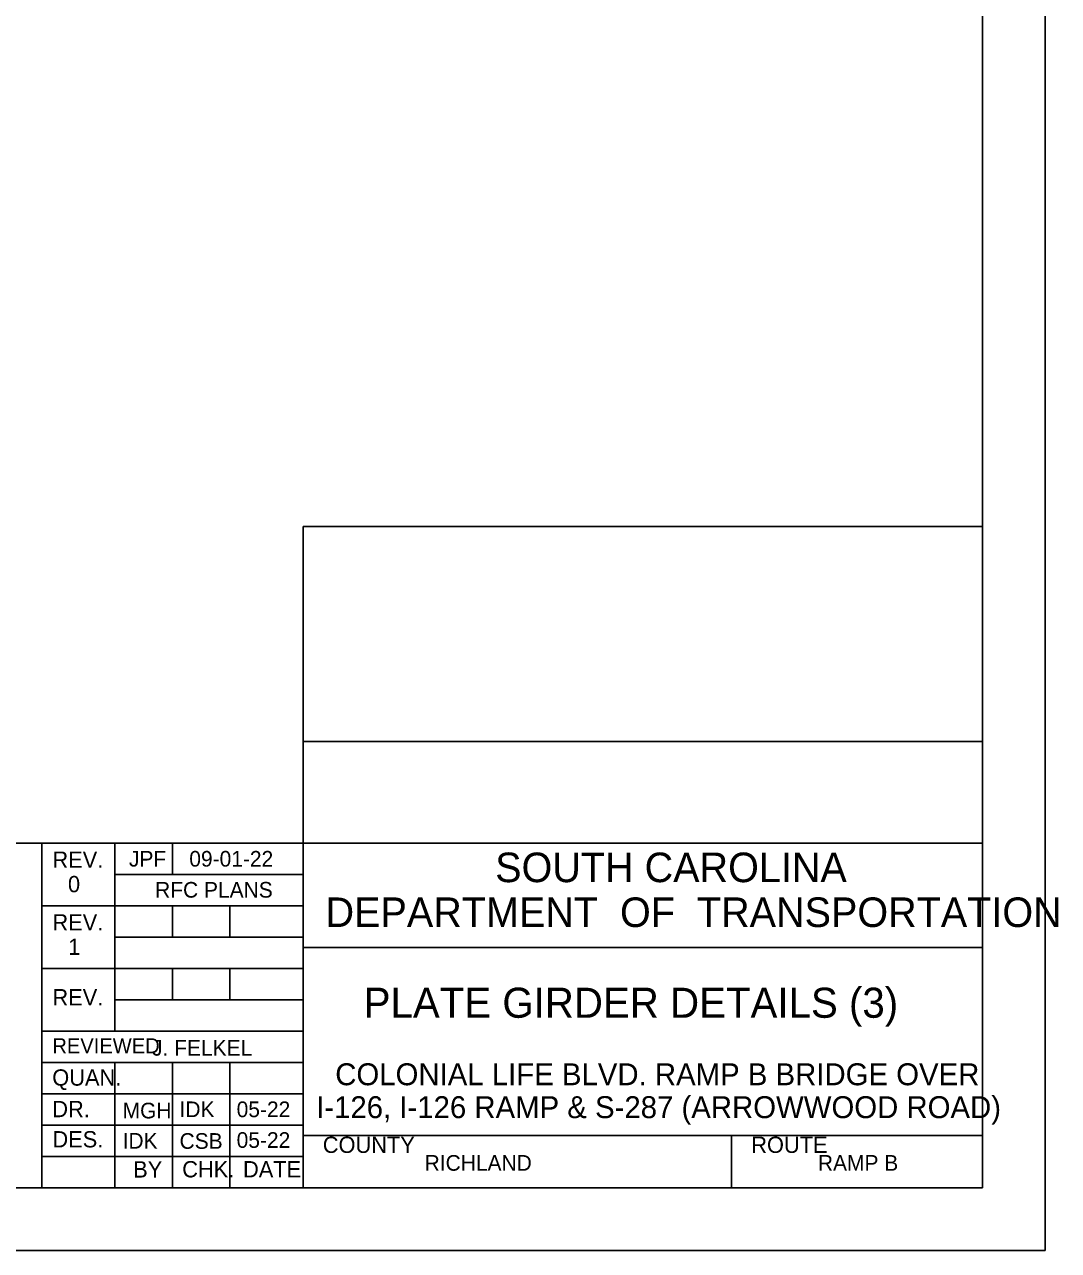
# Model space of a CAD drawing. Extents: x -305 to -161, y -187 to -99.
# Drawn here: x -193.73 to -160.75, y -187.49 to -148.37 of the extents above; entities that cross this region are included whole.
import ezdxf

# ---------------------------------------------------------------- set-up
doc = ezdxf.new("R2010")
doc.units = 0
for name, color, linetype in [('BR_BORDER LINES', 7, 'Continuous'), ('BR_TEXT', 7, 'Continuous'), ('Level 31', 7, 'Continuous')]:
    doc.layers.add(name, color=color, linetype=linetype)

msp = doc.modelspace()

# ---------------------------------------------------------------- linework, layer by layer
at = {"layer": 'BR_BORDER LINES'}
for p, q in [((-163.178, -185.489), (-163.178, -101.489)), ((-184.846, -185.489), (-184.846, -164.383)), ((-184.846, -164.383), (-163.178, -164.383)), ((-184.845, -171.242), (-163.178, -171.242)), ((-214.64, -174.489), (-193.18, -174.489)), ((-193.18, -185.489), (-193.18, -174.489)), ((-193.18, -174.489), (-163.178, -174.489)), ((-190.846, -174.489), (-190.846, -180.489)), ((-189.013, -175.489), (-189.013, -174.489)), ((-190.846, -175.489), (-184.846, -175.489)), ((-193.18, -176.489), (-184.846, -176.489)), ((-189.013, -177.489), (-189.013, -176.489)), ((-187.179, -177.489), (-187.179, -176.489)), ((-190.846, -177.489), (-184.846, -177.489)), ((-184.846, -177.822), (-184.846, -177.822)), ((-184.846, -177.823), (-163.178, -177.823)), ((-193.18, -178.489), (-184.846, -178.489)), ((-189.013, -179.489), (-189.013, -178.489)), ((-187.179, -179.489), (-187.179, -178.489)), ((-190.846, -179.489), (-184.846, -179.489)), ((-193.18, -180.489), (-184.846, -180.489)), ((-193.18, -181.489), (-184.846, -181.489)), ((-190.846, -181.489), (-190.846, -185.489)), ((-189.013, -181.489), (-189.013, -185.489)), ((-187.179, -181.489), (-187.179, -185.489)), ((-193.18, -182.489), (-184.846, -182.489)), ((-193.18, -183.489), (-184.846, -183.489)), ((-184.846, -183.823), (-163.178, -183.823)), ((-184.456, -183.823), (-163.178, -183.823)), ((-171.179, -185.489), (-171.179, -183.823)), ((-193.18, -184.489), (-184.846, -184.489)), ((-297.843, -185.489), (-163.178, -185.489))]:
    msp.add_line(p, q, dxfattribs=at)
at = {"layer": 'Level 31'}
msp.add_line((-174.011, -179.583), (-174.011, -179.583), dxfattribs=at)
msp.add_lwpolyline([(-305.176, -187.489), (-161.176, -187.489), (-161.176, -99.489), (-305.176, -99.489)], close=True, dxfattribs=at)

# ---------------------------------------------------------------- texts
at = {"layer": 'BR_TEXT'}
for s, height, p in [('REV.', 0.52, (-192.841, -175.277)), ('JPF', 0.5, (-190.4, -175.239)), ('09-01-22', 0.5, (-188.475, -175.239)), ('SOUTH CAROLINA', 0.94348, (-178.718, -175.735)), ('0', 0.52, (-192.345, -176.057)), ('RFC PLANS', 0.5, (-189.566, -176.229)), ('DEPARTMENT  OF  TRANSPORTATION', 0.94348, (-184.129, -177.166)), ('REV.', 0.52, (-192.841, -177.277)), ('1', 0.52, (-192.337, -178.057)), ('REV.', 0.52, (-192.841, -179.667)), ('PLATE GIRDER DETAILS (3)', 0.96, (-182.913, -180.063)), ('REVIEWED', 0.48, (-192.843, -181.195)), ('J. FELKEL', 0.5, (-189.664, -181.272)), ('COLONIAL LIFE BLVD. RAMP B BRIDGE OVER', 0.7, (-183.82, -182.216)), ('QUAN.', 0.52, (-192.846, -182.229)), ('I-126, I-126 RAMP & S-287 (ARROWWOOD ROAD) ', 0.7, (-184.429, -183.266)), ('DR.', 0.52, (-192.845, -183.235)), ('MGH', 0.5, (-190.602, -183.274)), ('IDK', 0.5, (-188.786, -183.234)), ('05-22', 0.5, (-186.965, -183.234)), ('DES.', 0.52, (-192.841, -184.2)), ('IDK', 0.5, (-190.602, -184.24)), ('CSB', 0.5, (-188.786, -184.245)), ('05-22', 0.5, (-186.965, -184.214)), ('COUNTY', 0.52, (-184.217, -184.376)), ('ROUTE', 0.52, (-170.55, -184.376)), ('BY', 0.52, (-190.265, -185.161)), ('CHK.', 0.52, (-188.701, -185.156)), ('DATE', 0.52, (-186.761, -185.156)), ('RICHLAND', 0.5, (-180.968, -184.944)), ('RAMP B', 0.5, (-168.424, -184.944))]:
    msp.add_text(s, height=height, dxfattribs=at).set_placement(p)

doc.saveas('drawing.dxf')
